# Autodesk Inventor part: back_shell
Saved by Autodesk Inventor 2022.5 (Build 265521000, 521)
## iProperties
Created: 2024-12
Part Number: back_shell
Material: Generic
Document SubType Name: Modeling
Designer: AdminForWorker
Density: 1 g/cm^3
Appearance: Default
Title: back_shell
Author: AdminForWorker
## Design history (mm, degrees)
feature "Body1"
body "Solid1"
